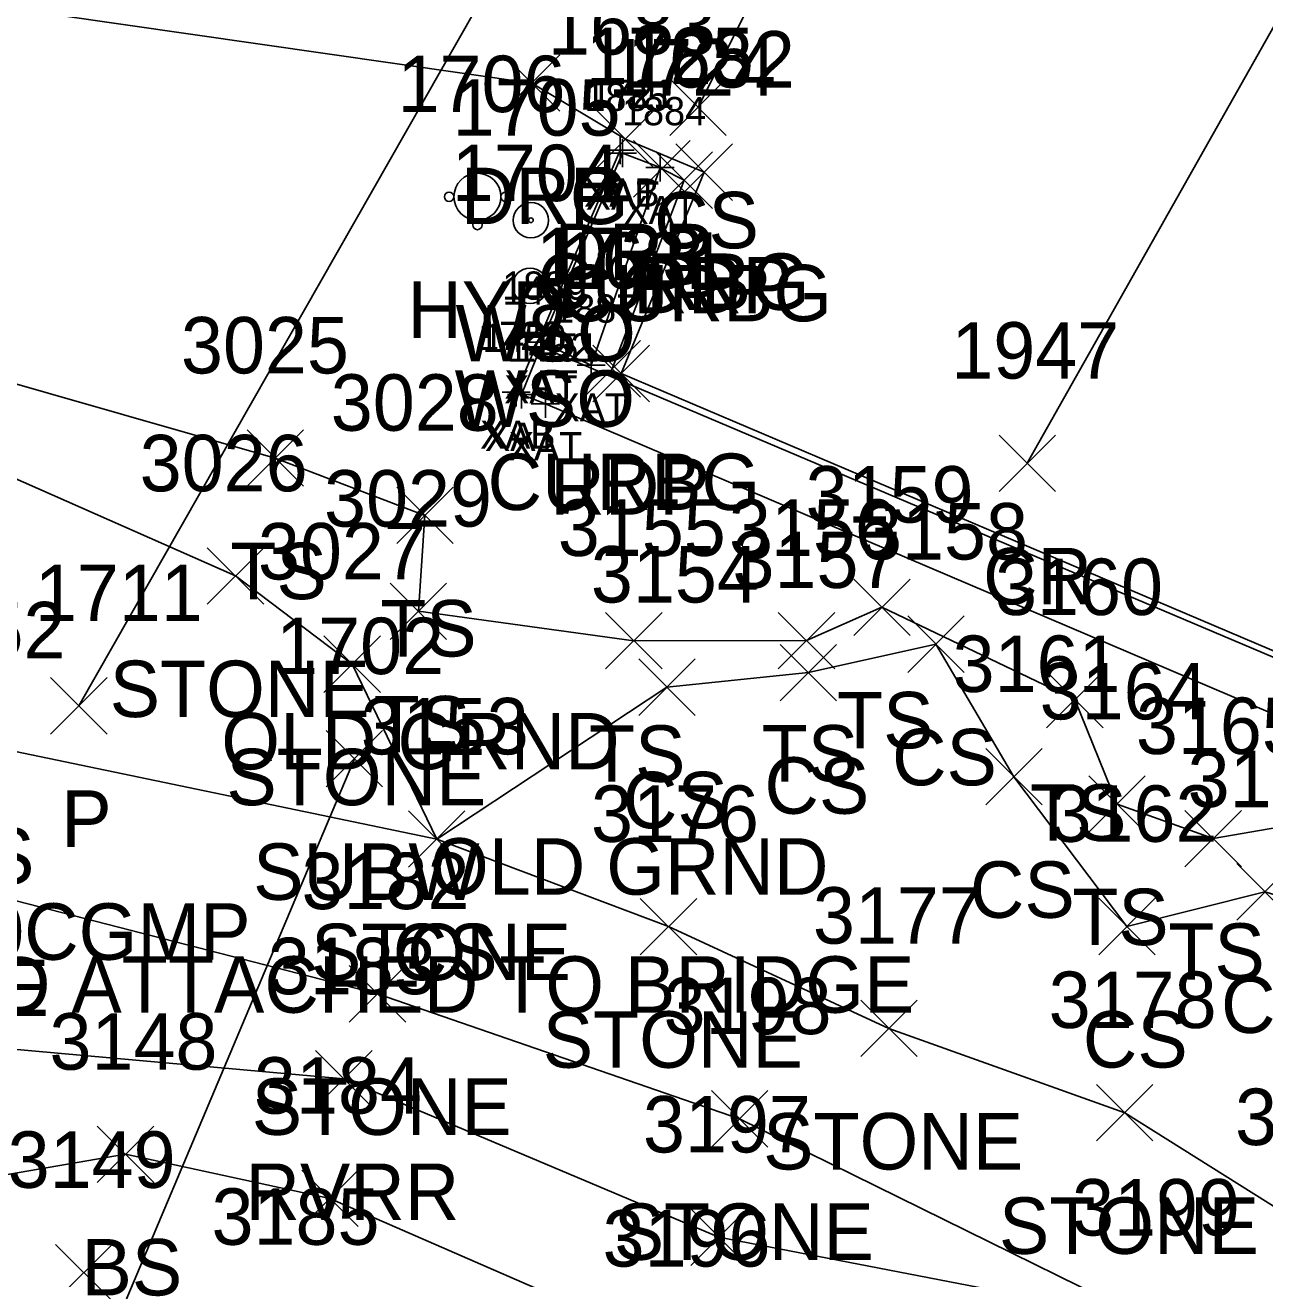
# Model space of a CAD drawing. Extents: x 462930 to 463548, y 29607 to 30453.
# Drawn here: x 463342.46 to 463355.85, y 30140.5 to 30154.04 of the extents above; entities that cross this region are included whole.
import ezdxf

# ---------------------------------------------------------------- set-up
doc = ezdxf.new("R2010")
doc.units = 0
for name, color, linetype in [('B_A', 7, 'Continuous'), ('B_I', 7, 'Continuous'), ('B_TIC', 7, 'Continuous'), ('BSUBM', 7, 'Continuous'), ('D_A', 7, 'Continuous'), ('D_C', 7, 'Continuous'), ('D_I', 7, 'Continuous'), ('D_TIC', 7, 'Continuous'), ('DCP', 7, 'Continuous'), ('L_A', 7, 'Continuous'), ('L_C', 7, 'Continuous'), ('L_I', 7, 'Continuous'), ('L_TIC', 7, 'Continuous'), ('LASF', 7, 'Continuous'), ('LAWE', 7, 'Continuous'), ('LELB', 7, 'Continuous'), ('P_A', 7, 'Continuous'), ('P_I', 7, 'Continuous'), ('P_TIC', 7, 'Continuous'), ('PET', 7, 'Continuous'), ('PRC', 7, 'Continuous'), ('R_A', 7, 'Continuous'), ('R_I', 7, 'Continuous'), ('R_TIC', 7, 'Continuous'), ('RC', 7, 'Continuous'), ('RDG', 7, 'Continuous'), ('RDP', 7, 'Continuous'), ('U_A', 7, 'Continuous'), ('U_C', 7, 'Continuous'), ('U_I', 7, 'Continuous'), ('U_TIC', 7, 'Continuous'), ('UW', 7, 'Continuous'), ('UWFH', 7, 'Continuous'), ('UWV', 7, 'Continuous')]:
    doc.layers.add(name, color=color, linetype=linetype)

msp = doc.modelspace()

# ---------------------------------------------------------------- linework, layer by layer
at = {"layer": 'B_TIC'}
for p, q in [((463348.887, 30152.69), (463348.91, 30152.69)), ((463348.911, 30152.657), (463348.934, 30152.657)), ((463349.318, 30152.502), (463349.341, 30152.502)), ((463348.029, 30150.565), (463348.052, 30150.565)), ((463348.033, 30150.618), (463348.056, 30150.618)), ((463348.574, 30150.37), (463348.597, 30150.37)), ((463347.763, 30150.075), (463347.786, 30150.075)), ((463347.823, 30150.053), (463347.846, 30150.053)), ((463348.079, 30149.95), (463348.102, 30149.95)), ((463348.081, 30149.95), (463348.104, 30149.95))]:
    msp.add_line(p, q, dxfattribs=at)
for points in [[(463348.886, 30152.538), (463348.886, 30152.842)], [(463348.734, 30152.69), (463349.038, 30152.69)], [(463348.91, 30152.505), (463348.91, 30152.809)], [(463348.758, 30152.657), (463349.062, 30152.657)], [(463349.317, 30152.35), (463349.317, 30152.654)], [(463349.165, 30152.502), (463349.469, 30152.502)], [(463348.028, 30150.413), (463348.028, 30150.717)], [(463348.032, 30150.466), (463348.032, 30150.77)], [(463347.876, 30150.565), (463348.18, 30150.565)], [(463347.88, 30150.618), (463348.184, 30150.618)], [(463348.573, 30150.218), (463348.573, 30150.522)], [(463348.421, 30150.37), (463348.725, 30150.37)], [(463347.762, 30149.923), (463347.762, 30150.227)], [(463347.822, 30149.901), (463347.822, 30150.205)], [(463347.61, 30150.075), (463347.914, 30150.075)], [(463347.67, 30150.053), (463347.974, 30150.053)], [(463348.078, 30149.798), (463348.078, 30150.102)], [(463348.08, 30149.798), (463348.08, 30150.102)], [(463347.926, 30149.95), (463348.23, 30149.95)], [(463347.928, 30149.95), (463348.232, 30149.95)]]:
    msp.add_lwpolyline(points, dxfattribs=at)
at = {"layer": 'BSUBM'}
for points in [[(463348.886, 30152.69), (463347.762, 30150.075)], [(463349.317, 30152.502), (463348.91, 30152.657), (463348.032, 30150.618), (463348.573, 30150.37)], [(463348.573, 30150.37), (463349.317, 30152.502)], [(463358.519, 30145.503), (463358.794, 30145.342), (463359.032, 30145.904), (463348.028, 30150.565), (463347.822, 30150.053), (463348.078, 30149.95), (463348.08, 30149.95)], [(463348.08, 30149.95), (463358.518, 30145.501)]]:
    msp.add_lwpolyline(points, dxfattribs=at)
at = {"layer": 'D_TIC'}
for points in [[(463342.735, 30146.385), (463343.345, 30146.995)], [(463343.345, 30146.385), (463342.735, 30146.995)]]:
    msp.add_lwpolyline(points, dxfattribs=at)
at = {"layer": 'DCP'}
msp.add_lwpolyline([(463354.963, 30167.616), (463343.04, 30146.69)], dxfattribs=at)
at = {"layer": 'L_TIC'}
for points in [[(463349.422, 30152.849), (463350.032, 30153.459)], [(463350.032, 30152.849), (463349.422, 30153.459)], [(463344.856, 30149.06), (463345.465, 30149.67)], [(463345.465, 30149.06), (463344.856, 30149.67)], [(463346.474, 30148.441), (463347.083, 30149.051)], [(463347.083, 30148.441), (463346.474, 30149.051)], [(463344.426, 30147.787), (463345.036, 30148.396)], [(463345.036, 30147.787), (463344.426, 30148.396)], [(463346.403, 30147.405), (463347.012, 30148.015)], [(463347.012, 30147.405), (463346.403, 30148.015)], [(463351.408, 30147.449), (463352.017, 30148.059)], [(463352.017, 30147.449), (463351.408, 30148.059)], [(463348.729, 30147.089), (463349.338, 30147.698)], [(463349.338, 30147.089), (463348.729, 30147.698)], [(463350.594, 30147.09), (463351.203, 30147.699)], [(463351.203, 30147.09), (463350.594, 30147.699)], [(463351.993, 30147.05), (463352.602, 30147.66)], [(463352.602, 30147.05), (463351.993, 30147.66)], [(463345.687, 30146.835), (463346.296, 30147.444)], [(463346.296, 30146.835), (463345.687, 30147.444)], [(463350.615, 30146.743), (463351.224, 30147.353)], [(463351.224, 30146.743), (463350.615, 30147.353)], [(463349.086, 30146.586), (463349.695, 30147.196)], [(463349.695, 30146.586), (463349.086, 30147.196)], [(463353.492, 30146.451), (463354.102, 30147.061)], [(463354.102, 30146.451), (463353.492, 30147.061)], [(463352.834, 30145.62), (463353.443, 30146.229)], [(463353.443, 30145.62), (463352.834, 30146.229)], [(463353.948, 30145.324), (463354.557, 30145.933)], [(463354.557, 30145.324), (463353.948, 30145.933)], [(463346.601, 30144.946), (463347.21, 30145.555)], [(463347.21, 30144.946), (463346.601, 30145.555)], [(463346.601, 30144.946), (463347.21, 30145.555)], [(463347.21, 30144.946), (463346.601, 30145.555)], [(463354.986, 30144.95), (463355.596, 30145.56)], [(463355.596, 30144.95), (463354.986, 30145.56)], [(463355.545, 30144.376), (463356.155, 30144.985)], [(463356.155, 30144.376), (463355.545, 30144.985)], [(463349.103, 30144), (463349.713, 30144.61)], [(463349.713, 30144), (463349.103, 30144.61)], [(463354.054, 30144.002), (463354.663, 30144.611)], [(463354.663, 30144.002), (463354.054, 30144.611)], [(463345.961, 30143.275), (463346.571, 30143.885)], [(463346.571, 30143.275), (463345.961, 30143.885)], [(463351.484, 30142.901), (463352.093, 30143.511)], [(463352.093, 30142.901), (463351.484, 30143.511)], [(463345.597, 30142.356), (463346.207, 30142.966)], [(463346.207, 30142.356), (463345.597, 30142.966)], [(463349.871, 30141.925), (463350.481, 30142.534)], [(463350.481, 30141.925), (463349.871, 30142.534)], [(463354.03, 30141.99), (463354.64, 30142.6)], [(463354.64, 30141.99), (463354.03, 30142.6)], [(463343.239, 30141.541), (463343.849, 30142.151)], [(463343.849, 30141.541), (463343.239, 30142.151)], [(463345.447, 30141.065), (463346.056, 30141.675)], [(463346.056, 30141.065), (463345.447, 30141.675)], [(463349.648, 30140.647), (463350.258, 30141.257)], [(463350.258, 30140.647), (463349.648, 30141.257)], [(463342.789, 30140.264), (463343.398, 30140.874)], [(463343.398, 30140.264), (463342.789, 30140.874)]]:
    msp.add_lwpolyline(points, dxfattribs=at)
at = {"layer": 'LASF'}
for points in [[(463335.666, 30151.825), (463334.307, 30149.365), (463333.551, 30148), (463337.382, 30145.968), (463341.269, 30144.863), (463346.266, 30143.58), (463350.176, 30142.23), (463354.589, 30140.054), (463359.587, 30137.022), (463360.802, 30137.163)], [(463335.666, 30151.825), (463339.994, 30150.186), (463344.731, 30148.092), (463345.991, 30147.14), (463346.905, 30145.251), (463349.408, 30144.305), (463351.788, 30143.206), (463354.335, 30142.295), (463356.35, 30141.031), (463357.426, 30140.903), (463358.46, 30140.002), (463361.001, 30139.273), (463362.41, 30138.437), (463365.572, 30136.833), (463366.432, 30136.349), (463367.765, 30135.728), (463368.18, 30135.769), (463368.592, 30135.381), (463370.057, 30136.689), (463370.978, 30134.911), (463374.408, 30132.631)]]:
    msp.add_lwpolyline(points, dxfattribs=at)
at = {"layer": 'LAWE'}
msp.add_lwpolyline([(463312.771, 30156.48), (463317.927, 30154.119), (463323.301, 30150.297), (463329.2, 30147.672), (463333.781, 30145.982), (463336.917, 30145.16), (463341.124, 30143.089), (463345.902, 30142.661), (463349.953, 30140.952), (463354.589, 30140.054), (463360.802, 30137.163), (463361.685, 30137.202), (463364.938, 30136.029), (463367.213, 30134.485), (463367.529, 30133.847), (463370.878, 30131.969), (463372.536, 30131.581), (463374.072, 30131.794), (463376.13, 30130.821), (463379.432, 30129.045)], dxfattribs=at)
at = {"layer": 'LELB'}
for points in [[(463355.606, 30164.89), (463349.727, 30153.154)], [(463315.632, 30161.314), (463319.611, 30159.411), (463323.098, 30158.045), (463326.567, 30156.56), (463329.582, 30155.13), (463332.054, 30154.159), (463333.762, 30152.444), (463336.134, 30152.447), (463340.253, 30150.769), (463345.161, 30149.365), (463346.778, 30148.746), (463346.708, 30147.71), (463349.033, 30147.393), (463350.898, 30147.395), (463351.713, 30147.754), (463353.797, 30146.756), (463354.253, 30145.629), (463355.291, 30145.255), (463356.709, 30145.503), (463357.92, 30145.112), (463358.601, 30144.516), (463359.186, 30143.714)], [(463311.51, 30154.564), (463317.305, 30152.12), (463328.108, 30145.648), (463332.48, 30143.532), (463335.24, 30142.565), (463339.678, 30141.183), (463343.544, 30141.846), (463345.752, 30141.37), (463349.534, 30139.719), (463354.026, 30138.661), (463359.587, 30137.022), (463361.306, 30136.712), (463364.334, 30135.56), (463366.649, 30133.733), (463367.281, 30133.213), (463370.369, 30131.577), (463372.89, 30130.394), (463376, 30129.47), (463379.084, 30127.97)], [(463338.725, 30147.014), (463341.902, 30146.288), (463346.905, 30145.251), (463349.39, 30146.891), (463350.92, 30147.048), (463352.297, 30147.355), (463353.139, 30145.924), (463354.358, 30144.307), (463355.85, 30144.681), (463357.539, 30144.184), (463357.985, 30144.223), (463357.945, 30143.102), (463357.652, 30141.391), (463358.461, 30140.69), (463361.001, 30139.273)]]:
    msp.add_lwpolyline(points, dxfattribs=at)
at = {"layer": 'P_TIC'}
for points in [[(463349.489, 30152.147), (463350.099, 30152.757)], [(463350.099, 30152.147), (463349.489, 30152.757)], [(463348.592, 30149.973), (463349.202, 30150.583)], [(463349.202, 30149.973), (463348.592, 30150.583)], [(463352.978, 30149.004), (463353.588, 30149.614)], [(463353.588, 30149.004), (463352.978, 30149.614)]]:
    msp.add_lwpolyline(points, dxfattribs=at)
at = {"layer": 'PET'}
for points in [[(463348.897, 30150.278), (463349.794, 30152.452)], [(463357.128, 30146.779), (463348.897, 30150.278)]]:
    msp.add_lwpolyline(points, dxfattribs=at)
at = {"layer": 'PRC'}
msp.add_lwpolyline([(463399.789, 30246.987), (463397.991, 30230.027), (463395.304, 30217.172), (463391.095, 30206.312), (463384.492, 30195.113), (463376.573, 30184.227), (463367.848, 30173.371), (463360.659, 30162.372), (463353.283, 30149.309)], dxfattribs=at)
at = {"layer": 'R_TIC'}
for points in [[(463347.626, 30153.11), (463348.236, 30153.72)], [(463348.236, 30153.11), (463347.626, 30153.72)], [(463347.626, 30153.11), (463348.236, 30153.72)], [(463348.236, 30153.11), (463347.626, 30153.72)], [(463348.637, 30152.504), (463349.247, 30153.114)], [(463349.247, 30152.504), (463348.637, 30153.114)], [(463349.031, 30152.184), (463349.641, 30152.794)], [(463349.641, 30152.184), (463349.031, 30152.794)], [(463349.489, 30152.147), (463350.099, 30152.757)], [(463350.099, 30152.147), (463349.489, 30152.757)], [(463349.272, 30152.061), (463349.882, 30152.671)], [(463349.882, 30152.061), (463349.272, 30152.671)], [(463348.495, 30150.023), (463349.105, 30150.633)], [(463349.105, 30150.023), (463348.495, 30150.633)]]:
    msp.add_lwpolyline(points, dxfattribs=at)
at = {"layer": 'RC'}
msp.add_lwpolyline([(463348.8, 30150.328), (463349.577, 30152.366), (463349.336, 30152.489)], dxfattribs=at)
at = {"layer": 'RDG'}
msp.add_lwpolyline([(463347.931, 30153.415), (463337.62, 30154.896), (463328.703, 30158.04), (463317.438, 30162.728), (463318.8, 30166.246), (463327.27, 30162.794), (463340.451, 30158.117), (463344.729, 30166.901), (463353.138, 30164.992), (463357.576, 30167.469)], dxfattribs=at)
at = {"layer": 'RDP'}
msp.add_lwpolyline([(463349.794, 30152.452), (463348.942, 30152.809), (463347.931, 30153.415)], dxfattribs=at)
at = {"layer": 'U_TIC'}
for points in [[(463345.711, 30145.813), (463346.321, 30146.423)], [(463346.321, 30145.813), (463345.711, 30146.423)]]:
    msp.add_lwpolyline(points, dxfattribs=at)
at = {"layer": 'UW'}
msp.add_lwpolyline([(463346.016, 30146.118), (463335.205, 30120.517)], dxfattribs=at)
at = {"layer": 'UWFH'}
msp.add_line((463347.344, 30152.187), (463347.344, 30152.187), dxfattribs=at)
for centre, radius in [((463347.344, 30152.187), 0.254), ((463347.039, 30152.187), 0.0508), ((463347.649, 30152.187), 0.0508), ((463347.344, 30151.882), 0.0508)]:
    msp.add_circle(centre, radius, dxfattribs=at)
at = {"layer": 'UWV'}
for centre, radius in [((463347.922, 30151.933), 0.191), ((463347.922, 30151.933), 0.0254), ((463347.913, 30151.226), 0.191), ((463347.913, 30151.226), 0.0254)]:
    msp.add_circle(centre, radius, dxfattribs=at)

# ---------------------------------------------------------------- texts
at = {"layer": 'B_A'}
for s, p in [('XAB', (463348.496, 30152.08)), ('XAT', (463348.515, 30152.047)), ('XAT', (463348.922, 30151.892)), ('XAT', (463347.633, 30149.955)), ('XAT', (463347.637, 30150.008)), ('XAT', (463348.178, 30149.76)), ('XAB', (463347.372, 30149.465)), ('XAT', (463347.427, 30149.443)), ('XAT', (463347.683, 30149.34)), ('XAT', (463347.685, 30149.34))]:
    msp.add_text(s, height=0.3048, dxfattribs=at).set_placement(p)
at = {"layer": 'B_I'}
for s, p in [('1885', (463348.5, 30153.114)), ('1721', (463348.562, 30153.147)), ('1884', (463348.907, 30152.959)), ('1886', (463347.613, 30151.075)), ('1449', (463347.616, 30151.022)), ('1887', (463348.163, 30150.827)), ('1722', (463347.352, 30150.532)), ('1450', (463347.398, 30150.51)), ('1452', (463347.67, 30150.407)), ('1451', (463347.754, 30150.407))]:
    msp.add_text(s, height=0.3048, dxfattribs=at).set_placement(p)
at = {"layer": 'D_A'}
msp.add_text('P', height=0.61, dxfattribs=at).set_placement((463342.85, 30145.166))
at = {"layer": 'D_C'}
msp.add_text('460CGMP', height=0.6096, dxfattribs=at).set_placement((463341.089, 30143.947))
at = {"layer": 'D_I'}
msp.add_text('1711', height=0.6096, dxfattribs=at).set_placement((463342.565, 30147.604))
at = {"layer": 'L_A'}
for s, p in [('CS', (463349.252, 30151.63)), ('TS', (463344.676, 30147.841)), ('TS', (463346.294, 30147.222)), ('STONE', (463343.373, 30146.568)), ('TS', (463346.223, 30146.186)), ('TS', (463351.228, 30146.23)), ('TS', (463348.549, 30145.869)), ('TS', (463350.414, 30145.871)), ('CS', (463351.822, 30145.831)), ('STONE', (463344.633, 30145.616)), ('CS', (463350.444, 30145.524)), ('CS', (463348.915, 30145.367)), ('TS', (463353.312, 30145.232)), ('CS', (463341.427, 30144.764)), ('CS', (463352.663, 30144.4)), ('TS', (463353.768, 30144.105)), ('STONE', (463345.547, 30143.727)), ('CS', (463346.43, 30143.727)), ('TS', (463354.806, 30143.731)), ('STONE', (463339.91, 30143.339)), ('CS', (463355.375, 30143.157)), ('STONE', (463348.05, 30142.781)), ('CS', (463353.883, 30142.783)), ('STONE', (463344.907, 30142.056)), ('STONE', (463350.43, 30141.682)), ('RVRR', (463344.839, 30141.137)), ('STONE', (463348.817, 30140.706)), ('STONE', (463352.977, 30140.771)), ('BS', (463343.069, 30140.322))]:
    msp.add_text(s, height=0.6096, dxfattribs=at).set_placement(p)
at = {"layer": 'L_C'}
for p in [(463344.578, 30146.003), (463346.833, 30144.65)]:
    msp.add_text('OLD GRND', height=0.6096, dxfattribs=at).set_placement(p)
at = {"layer": 'L_I'}
for s, p in [('3025', (463344.143, 30150.279)), ('3028', (463345.761, 30149.66)), ('3026', (463343.697, 30149.006)), ('3029', (463345.688, 30148.625)), ('3159', (463350.889, 30148.668)), ('3155', (463348.213, 30148.308)), ('3156', (463350.061, 30148.309)), ('3158', (463351.477, 30148.269)), ('3027', (463344.974, 30148.054)), ('3157', (463350.099, 30147.962)), ('3154', (463348.57, 30147.805)), ('3160', (463352.935, 30147.67)), ('3152', (463341.081, 30147.202)), ('3161', (463352.476, 30146.839)), ('3164', (463353.417, 30146.543)), ('3153', (463346.085, 30146.165)), ('3153', (463346.085, 30146.165)), ('3165', (463354.456, 30146.169)), ('3163', (463355.015, 30145.595)), ('3176', (463348.571, 30145.22)), ('3162', (463353.523, 30145.221)), ('3182', (463345.445, 30144.494)), ('3177', (463350.968, 30144.121)), ('3183', (463345.082, 30143.575)), ('3198', (463349.355, 30143.144)), ('3178', (463353.514, 30143.21)), ('3148', (463342.723, 30142.76)), ('3184', (463344.931, 30142.285)), ('3179', (463355.527, 30141.946)), ('3197', (463349.132, 30141.866)), ('3149', (463342.271, 30141.484)), ('3199', (463353.766, 30140.969)), ('3199', (463353.766, 30140.969)), ('3185', (463344.473, 30140.869)), ('3196', (463348.696, 30140.634))]:
    msp.add_text(s, height=0.6096, dxfattribs=at).set_placement(p)
at = {"layer": 'P_A'}
for s, p in [('RDP', (463349.028, 30150.928)), ('RDP', (463348.131, 30148.754)), ('CR', (463352.805, 30147.785))]:
    msp.add_text(s, height=0.6096, dxfattribs=at).set_placement(p)
at = {"layer": 'P_I'}
for s, p in [('1682', (463348.959, 30153.366)), ('1681', (463348.235, 30151.192)), ('1947', (463352.462, 30150.223))]:
    msp.add_text(s, height=0.6096, dxfattribs=at).set_placement(p)
at = {"layer": 'R_A'}
for s, p in [('DRG', (463347.165, 30151.891)), ('DRP', (463347.165, 30151.891)), ('DRP', (463348.176, 30151.285)), ('CURBG', (463347.99, 30150.965)), ('CURBG', (463348.231, 30150.842)), ('DRP', (463349.028, 30150.928)), ('CURBG', (463347.454, 30148.804))]:
    msp.add_text(s, height=0.6096, dxfattribs=at).set_placement(p)
at = {"layer": 'R_I'}
for s, p in [('1683', (463348.107, 30153.723)), ('1725', (463348.515, 30153.403)), ('1724', (463348.756, 30153.28)), ('1682', (463348.959, 30153.366)), ('1723', (463347.979, 30151.242))]:
    msp.add_text(s, height=0.6096, dxfattribs=at).set_placement(p)
at = {"layer": 'U_A'}
for s, p in [('HYD', (463346.588, 30150.663)), ('WSO', (463347.108, 30150.409)), ('WSO', (463347.099, 30149.702)), ('SUBW', (463344.922, 30144.594))]:
    msp.add_text(s, height=0.6096, dxfattribs=at).set_placement(p)
at = {"layer": 'U_C'}
msp.add_text('EXPOSED ATTACHED TO BRIDGE', height=0.6096, dxfattribs=at).set_placement((463338.792, 30143.375))
at = {"layer": 'U_I'}
for s, p in [('1706', (463346.482, 30153.101)), ('1705', (463347.077, 30152.847)), ('1704', (463347.068, 30152.14)), ('1702', (463345.171, 30147.032))]:
    msp.add_text(s, height=0.6096, dxfattribs=at).set_placement(p)

doc.saveas('drawing.dxf')
